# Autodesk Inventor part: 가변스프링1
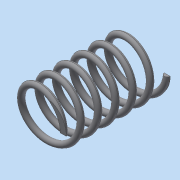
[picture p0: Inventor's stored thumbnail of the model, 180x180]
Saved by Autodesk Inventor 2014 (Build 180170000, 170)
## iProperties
Created: 2023-01
Part Number: 가변스프링1
Material: 일반
Document SubType Name: Modeling
Designer: dg
Density: 1 g/cm^3
Appearance: 기본값
Mass: 0.990077 g
Surface Area: 20.0872 cm^2
Volume: 0.990077 cm^3
Author: dg
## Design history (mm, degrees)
sketch "스케치1"
  geometry: L1 (8.5, 0)-(0, 0); L2 (0, 0)-(0, 26.33); L3 (0, 26.33)-(8.5, 26.33); C1 r 1 at (8.5, 0)
  constraints: 6 end point, 1 centre point, 1 coincident, 1 horizontal, 1 parallel, 1 vertical, 1 vertical alignment
  dimensions: "d0" = 2 diameter of C1; "d1" = 26.33013 distance of L1.end L2.end (derived); "d2" = 17 diameter of L1.start L2
feature "코일1" sketch "스케치1" pitch "d3" = 10; turns "d5" = 6; dims "d4" = 26.33013 (= d1), "d6" = 0, angle "d7" = 90 deg, angle "d8" = 90 deg, "d9" = 0, "d10" = 0
node "작업 평면1"
node "작업 평면2"
feature "분할1"
feature "분할2"
node "솔리드1"
other parameters: "d11" = 90 deg, "d12" = 90 deg
